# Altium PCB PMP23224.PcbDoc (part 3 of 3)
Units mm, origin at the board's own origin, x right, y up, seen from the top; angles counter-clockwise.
Board outline 180 x 75 mm, 4 copper layers (Top Layer, Signal Layer 1, Signal Layer 2, Bottom Layer), stack 1.565 mm thick; 189 components, 98 nets, 443 pads, 89 vias.
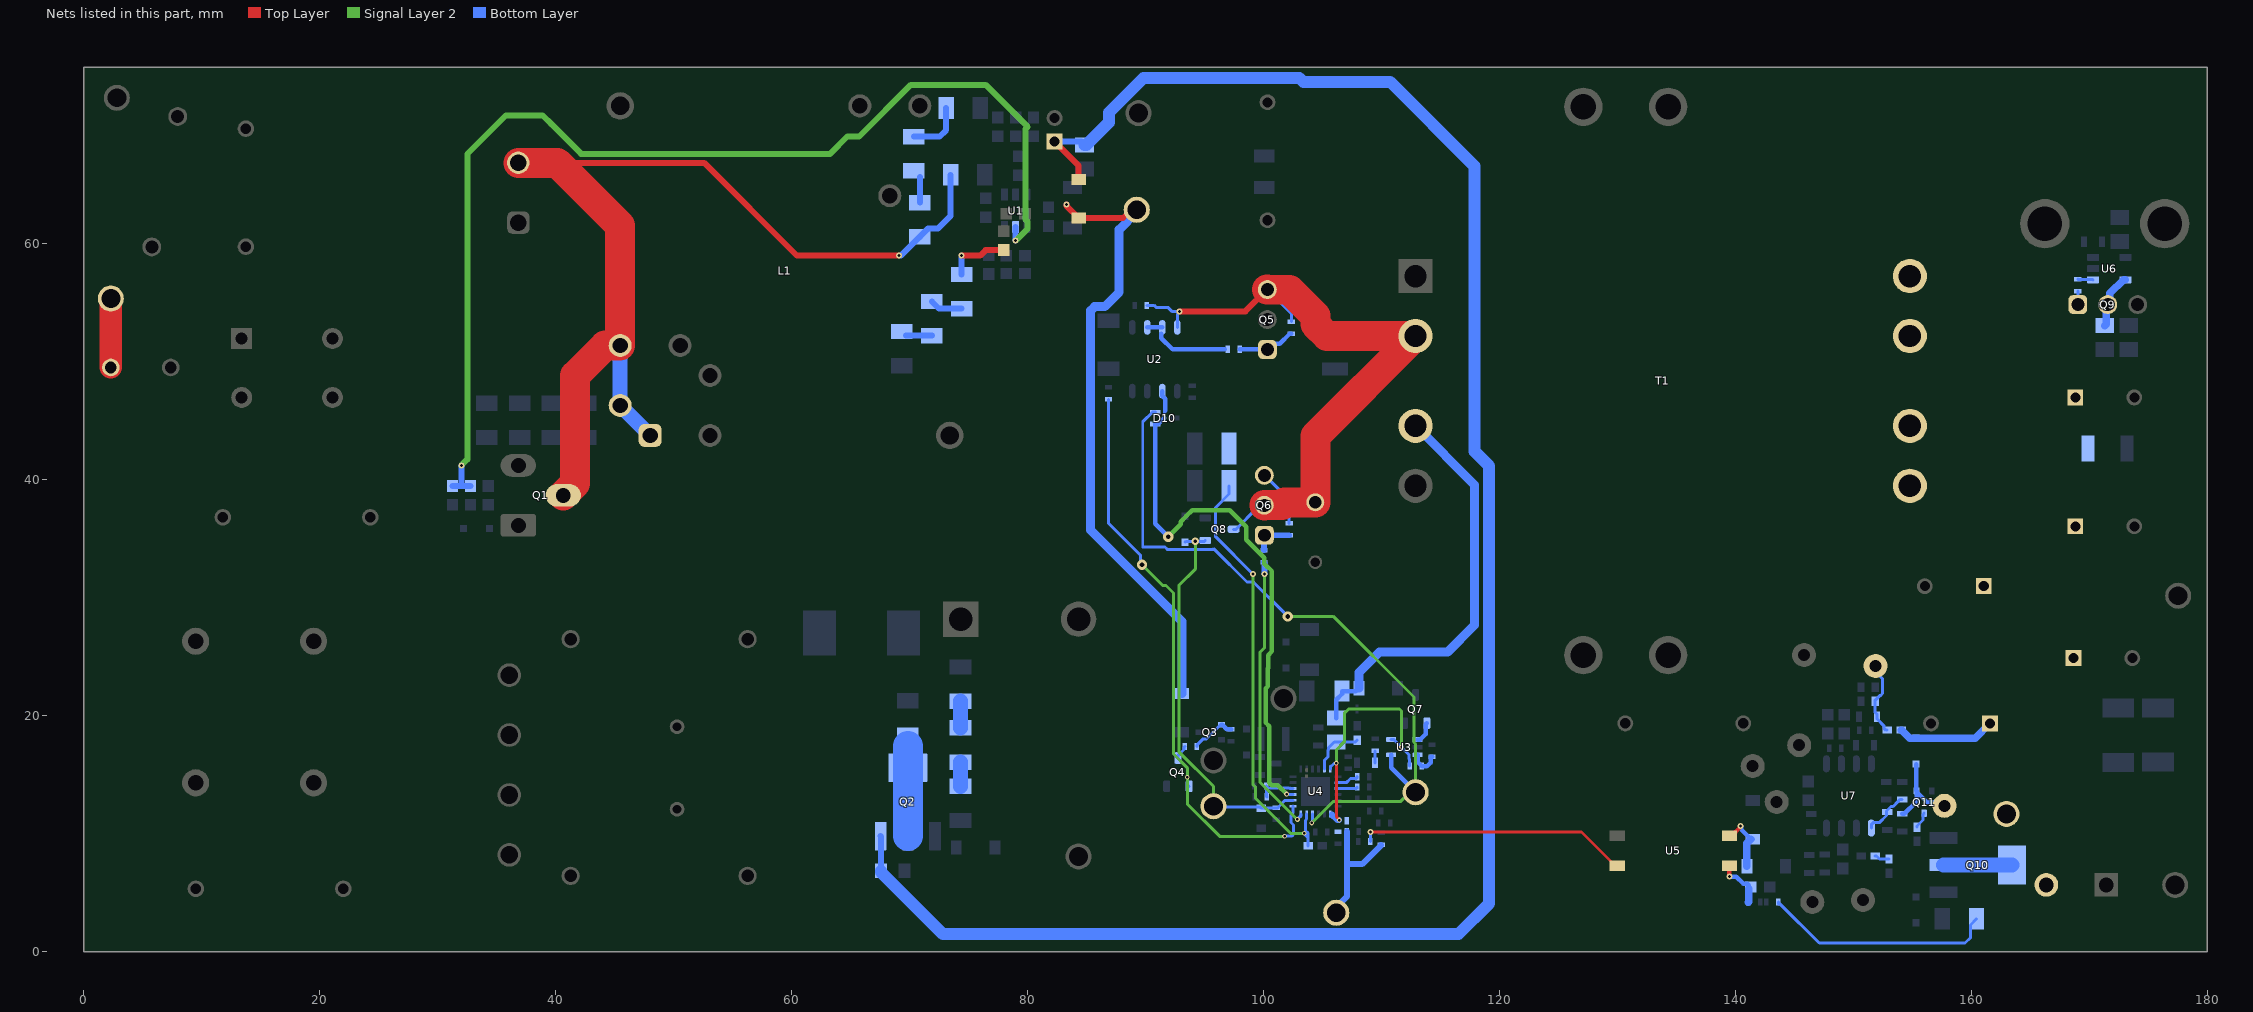
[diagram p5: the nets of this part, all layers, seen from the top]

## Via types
v1: diameter 0.508, hole 0.254, Top Layer to Bottom Layer, 41 vias
v2: diameter 0.406, hole 0.203, Top Layer to Bottom Layer, 23 vias
v3: diameter 1.27, hole 0.711, Top Layer to Bottom Layer, 12 vias
v4: diameter 0.5, hole 0.2, Top Layer to Bottom Layer, 5 vias
v5: diameter 0.864, hole 0.406, Top Layer to Bottom Layer, 4 vias
v6: diameter 2.54, hole 1.27, Top Layer to Bottom Layer, 2 vias
v7: diameter 0.635, hole 0.305, Top Layer to Bottom Layer, 2 vias

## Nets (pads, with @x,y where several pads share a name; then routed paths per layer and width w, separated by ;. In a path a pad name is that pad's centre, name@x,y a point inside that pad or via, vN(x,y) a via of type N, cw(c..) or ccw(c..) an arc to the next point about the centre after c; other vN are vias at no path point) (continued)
NetD19_2: D19.2 Q11.1 R68.2 TP20.1 | length 7.7
  Bottom Layer w0.381: R68.2@154.145,11.696 154.336,11.696 155.363,12.724 Q11.1@155.363,13.576 ; D19.2@155.326,15.902 155.345,15.884 155.345,13.659 Q11.1@155.363,13.641 Q11.1@155.363,13.576 ; TP20.1@157.734,12.369 157.418,12.685 156.253,12.685 Q11.1@155.363,13.576
NetF1_1: F1.1 TP_L1.1 | length 5.8
  Top Layer w1.905: F1.1@2.286,49.53 TP_L1.1@2.286,55.372
NetQ2_2: Q2.2 Q2.4 R20.1 | length 7.7
  Bottom Layer w2.54: Q2.2@69.85,9.8 Q2.4@69.85,15.6 69.85,17.458
NetQ3_1: Q3.1 R25.1 R26.2 | length 3.9
  Bottom Layer w0.254: R26.2@94.353,17.389 94.353,17.503 94.894,18.044 95.164,18.044 96.376,19.256 Q3.1@96.441,19.256
  Bottom Layer w0.381: Q3.1@96.441,19.256 96.506,19.256 96.899,18.864 R25.1@97.255,18.864
NetQ4_3: Q4.3 R26.1 | length 1.2
  Bottom Layer w0.254: Q4.3@92.745,16.421 92.745,16.621 93.273,17.15 93.273,17.325 R26.1@93.337,17.389
NetQ5_1: Q5.1 R28.2 R29.2 | length 5
  Bottom Layer w0.381: R28.2@97.974,51.067 100.317,51.067 Q5.1@100.33,51.054 100.81,51.534 101.377,51.534 102.248,52.405 R29.2@102.362,52.405
NetQ6_1: Q6.1 R30.2 R31.2 | length 3.4
  Bottom Layer w0.508: R30.2@100.055,34.036 100.065,34.047 100.065,35.295 Q6.1@100.076,35.306 R31.2@102.181,35.306
NetQ7_1: Q7.1 U3.1 | length 1.8
  Bottom Layer w0.381: U3.1@113.078,17.988 113.303,17.988 113.744,18.428 113.744,19.265 Q7.1@113.853,19.374
NetQ9_1: Q9.1 R51.1 | length 1.1
  Bottom Layer w0.254: Q9.1@169.037,54.864 R51.1@169.037,56.007
NetQ11_3: Q11.3 R66.1 | length 1.4
  Bottom Layer w0.254: R66.1@155.401,10.564 155.401,10.664 155.905,11.168 155.905,11.633 Q11.3@156.013,11.741
NetR1_1: R1.1 R2.2 | length 2.2
  Bottom Layer w0.508: R1.1@70.866,63.507 R2.2@70.866,65.687
NetR2_1: R2.1 R5.2 | length 4.8
  Bottom Layer w0.508: R2.1@70.358,69.095 72.538,69.095 73.099,69.656 R5.2@73.099,71.521
NetR3_1: R3.1 R7.1 U1.5 | length 95.4
  Signal Layer 2 w0.508: v1(32.004,41.229) 32.512,41.737 32.512,67.63 35.775,70.893 38.901,70.893 39.609,70.185 39.624,70.185 42.164,67.645 63.261,67.645 64.731,69.115 65.732,69.115 70.104,73.487 76.454,73.487 80.01,69.931 79.81,69.731 79.81,62.091 80.01,61.891 80.01,61.295 v1(78.994,60.279)
  Bottom Layer w0.508: R7.1@31.242,39.489 32.004,39.489 ; v1(32.004,41.229) 32.004,39.489 ; R3.1@32.766,39.489 32.004,39.489 ; v1(78.994,60.279) U1.5@78.994,61.444
NetR6_1: R6.1 R9.2 | length 2.2
  Bottom Layer w0.508: R6.1@69.702,52.225 R9.2@71.882,52.225
NetR9_1: R9.1 R15.2 | length 2.8
  Bottom Layer w0.508: R9.1@71.882,55.125 72.496,54.511 R15.2@74.422,54.511
NetR15_1: R15.1 R16.2 | length 5.3
  Top Layer w0.508: v1(74.422,59.009) 75.984,59.009 76.454,59.479 77.216,59.479 R16.2@77.978,59.479
  Bottom Layer w0.508: R15.1@74.422,57.411 v1(74.422,59.009)
NetR19_1: R19.1 R22.2 | length 2.3
  Bottom Layer w1.27: R22.2@74.328,18.976 R19.1@74.328,21.237
NetR22_1: R22.1 R23.2 | length 2.1
  Bottom Layer w1.27: R23.2@74.328,14.021 R22.1@74.328,16.076
NetR28_1: R28.1 U2.6 U2.7 | length 7.4
  Bottom Layer w0.381: U2.6@90.154,52.927 U2.7@91.424,52.927 ; U2.7@91.339,52.407 91.339,52.016 92.301,51.054 96.704,51.054
NetR32_1: R32.1 R34.1 U3.3 | length 2.6
  Bottom Layer w0.381: U3.3@113.078,16.688 113.078,16.085 113.459,15.704 113.855,15.704 114.186,16.034 114.186,16.51 R34.1@114.3,16.51
NetR41_2: R41.2 U5.4 | length 22.9
  Top Layer w0.254: v1(109.058,10.147) 126.959,10.147 129.802,7.303 U5.4@130.002,7.303
  Bottom Layer w0.254: R41.2@109.058,9.332 v1(109.058,10.147)
NetR43_2: R43.2 RT1.1 | length 1
  Bottom Layer w0.254: RT1.1@109.474,16.002 R43.2@109.474,17.018
NetR51_2: R51.2 U6.1 | length 1.3
  Bottom Layer w0.254: R51.2@169.037,57.023 169.067,56.992 170.298,56.992 U6.1@170.329,56.962
NetR52_1: R52.1 R53.2 R55.2 TP13.1 | length 6.5
  Bottom Layer w0.254: TP13.1@151.892,24.229 151.892,23.748 152.489,23.151 152.489,21.893 152.298,21.701 152.235,21.701 151.862,21.328 R53.2@151.862,21.228 151.862,20.275 152.024,20.113 R55.2@152.024,19.923 152.024,19.732 152.591,19.165 152.591,18.953 152.764,18.78 R52.1@152.864,18.78
NetR61_1: R61.1 R65.2 U7.5 | length 4
  Bottom Layer w0.254: U7.5@151.53,10.483 151.53,10.774 151.69,10.934 152.211,10.934 152.818,11.541 152.818,11.731 152.818,11.922 153.21,12.314 153.388,12.314 153.822,12.747 153.822,12.768 153.945,12.891 R61.1@154.145,12.891
NetR63_1: R63.1 R64.2 | length 1.3
  Bottom Layer w0.254: R64.2@151.862,8.112 151.962,8.112 152.216,7.858 R63.1@153.04,7.858
OPTO_AN: R58.1 R59.1 U5.1 | length 4.3
  Top Layer w0.381: v1(139.502,6.39) U5.1@139.502,7.303
  Bottom Layer w0.381: v1(139.502,6.39) 139.527,6.365 140.093,6.365 140.694,5.764 141.009,5.764 141.136,5.637 R58.1@141.136,5.322
  Bottom Layer w0.635: R59.1@141.102,4.21 141.136,4.243 R58.1@141.136,5.322
OPTO_CA: D17.2 D18.2 U5.2 | length 5.4
  Top Layer w0.381: U5.2@139.502,9.843 139.702,9.843 140.438,10.579 140.438,10.626 v1(140.462,10.651)
  Bottom Layer w0.381: v1(140.462,10.651) 140.486,10.626 140.486,10.378 141.325,9.539 D17.2@141.478,9.539
  Bottom Layer w0.635: D18.2@140.989,7.258 140.989,9.202 D17.2@141.325,9.539
P13: C28.1 D14.1 D15.1 Q8.1 TP6.1 U4.14 | length 33.2
  Signal Layer 2 w0.254: v7(94.22,34.804) 94.22,32.433 92.83,31.043 92.83,16.944 95.758,14.017 TP6.1@95.758,12.334
  Bottom Layer w0.254: D14.1@93.345,34.714 93.42,34.789 94.991,34.789 Q8.1@95.066,34.864 ; TP6.1@95.758,12.334 95.842,12.25 99.738,12.25 D15.1@99.822,12.166 99.835,12.179 101.079,12.179 C28.1@101.092,12.192 101.206,12.192 101.27,12.255 101.27,12.271 101.833,12.834 U4.14@102.514,12.834
PWMH: D10.1 U2.2 U4.15 | length 47.1
  Signal Layer 2 w0.381: v5(91.929,35.178) 92.991,36.239 92.991,36.452 93.475,36.937 93.475,36.948 93.96,37.433 97.129,37.433 98.546,36.017 98.546,34.919 100.054,33.41 100.075,33.41 ; 100.076,33.409 100.076,32.872 100.299,32.648 100.343,32.648 100.72,32.271 100.72,25.461 100.406,25.146 100.406,24.036 100.382,24.012 100.382,22.51 100.212,22.34 100.212,19.396 100.484,19.123 100.484,16.73 100.484,14.337 100.708,14.114 101.216,14.114 v2(101.966,13.364)
  Bottom Layer w0.254: 91.576,45.278 91.576,45.368 91.631,45.423 91.631,45.811 91.686,45.866 ; v2(101.966,13.364) 101.989,13.341 102.507,13.341 U4.15@102.514,13.334
  Bottom Layer w0.381: U2.2@91.424,47.527 91.424,47.137 91.686,46.875 91.686,45.866 ; 91.576,45.278 91.576,45.23 91.084,44.739 D10.1@90.834,44.739 90.834,36.272 v5(91.929,35.178)
PWML: R30.1 U4.12 | length 23.9
  Signal Layer 2 w0.254: v1(100.076,32.004) 100.076,25.75 99.694,25.368 99.694,14.396 v2(102.875,11.215)
  Bottom Layer w0.254: v2(102.875,11.215) 102.875,11.229 103.164,11.518 U4.12@103.164,11.684
  Bottom Layer w0.508: R30.1@100.055,33.02 100.076,32.999 v1(100.076,32.004)
RDM: R44.2 U4.3 | length 1.7
  Bottom Layer w0.254: U4.3@106.314,13.834 107.886,13.834 107.95,13.897 R44.2@107.95,13.97
REF: C27.2 C32.1 R32.2 R40.2 R46.2 TP9.1 U3.5 U4.7 U4.24 | length 33
  Top Layer w0.254: v2(106.172,15.993) 106.172,11.453 106.422,11.203 v2(106.422,11.162)
  Signal Layer 2 w0.254: v2(106.172,15.993) 106.172,17.106 106.857,17.792 106.857,20.21 107.222,20.574 111.531,20.574 111.704,20.401 v2(111.704,17.366)
  Bottom Layer w0.254: U4.24@105.664,15.484 105.664,15.65 105.978,15.964 106.143,15.964 v2(106.172,15.993) ; U3.5@110.828,17.988 111.053,17.988 112.326,16.715 112.326,16.382 112.395,16.313 R32.2@112.395,15.748
  Bottom Layer w0.508: 105.803,11.626 106.268,11.162 v2(106.422,11.162) ; TP9.1@106.172,3.302 106.172,3.763 107.075,4.665 107.075,7.426 ; R40.2@107.075,10.186 107.075,7.426 ; R46.2@109.982,9.052 109.982,9.039 108.368,7.426 107.075,7.426
RTZ: R42.2 U4.2 | length 1.9
  Bottom Layer w0.254: U4.2@106.314,14.334 107.026,14.334 107.379,14.687 107.886,14.687 107.95,14.75 R42.2@107.95,14.834
RUN: D10.2 TP8.1 U3.4 U4.10 | length 63.2
  Signal Layer 2 w0.254: v5(102.052,28.429) 105.915,28.429 112.754,21.59 112.754,17.727 112.903,17.579 TP8.1@112.903,13.521 112.395,13.521 111.598,12.725 105.897,12.725 v2(104.094,10.922)
  Bottom Layer w0.254: D10.2@90.834,45.739 90.584,45.739 89.768,44.922 89.768,34.308 91.664,34.308 91.884,34.087 95.721,34.087 95.793,34.159 98.599,31.353 99.129,31.353 v5(102.052,28.429) ; v2(104.094,10.922) 104.094,10.963 104.157,11.026 104.157,11.677 U4.10@104.164,11.684
  Bottom Layer w0.381: U3.4@110.828,16.688 110.828,15.596 TP8.1@112.903,13.521
S13: Q4.1 R27.1 U4.13 | length 50.8
  Signal Layer 2 w0.254: v5(89.694,32.811) 91.462,31.043 91.746,31.043 92.376,30.413 92.376,16.756 93.545,15.588 v2(93.545,14.783) 93.545,12.522 96.285,9.782 v2(101.793,9.782)
  Bottom Layer w0.254: R27.1@86.868,46.817 86.868,36.321 89.578,33.612 89.578,32.927 v5(89.694,32.811) ; v2(93.545,14.783) 93.574,14.754 93.574,14.142 Q4.1@93.695,14.021 ; v2(101.793,9.782) 101.822,9.811 102.434,9.811 102.555,9.932 102.545,9.942 102.545,10.745 102.345,10.945 102.345,11.577 102.514,11.746 U4.13@102.514,12.334
SWS: C26.1 R37.1 U4.16 | length 3.2
  Bottom Layer w0.254: C26.1@100.246,14.04 100.246,13.934 C26.1@100.266,13.914 ; R37.1@100.286,13.13 100.266,13.15 C26.1@100.266,13.914 ; U4.16@102.514,13.834 102.507,13.841 102.239,13.841 102.186,13.894 101.695,13.894 101.672,13.871 100.309,13.871 C26.1@100.266,13.914
Vaux: D9.2 D11.2 R38.2 T1.3 | length 35.8
  Bottom Layer w0.381: R38.2@106.172,19.812 106.172,21.356 106.664,21.848 D9.2@106.664,22.098 107.837,22.098 D11.2@108.091,22.352
  Bottom Layer w0.762: D11.2@108.091,22.352 108.091,23.661 109.83,25.4 115.603,25.4 117.889,27.686 117.889,39.579 T1.3@112.89,44.577
VCC_PFC: C11.1 C16.1 D5.1 Q2.3 R17.2 | length 166.2
  Top Layer w0.508: C11.1@82.296,68.677 84.328,66.645 D5.1@84.328,65.472
  Bottom Layer w0.508: Q2.3@67.55,9.8 67.563,9.787 67.563,6.871 C16.1@67.575,6.858 ; C11.1@82.296,68.677 R17.2@84.566,68.677
  Bottom Layer w1.016: C16.1@67.575,6.858 67.575,6.749 72.835,1.489 116.526,1.489 119.126,4.089 119.126,41.181 117.889,42.418 117.889,66.596 110.744,73.741 103.377,73.741 103.035,74.083 89.838,74.083 86.893,71.137 86.893,70.298 85.001,68.407 R17.2@84.836,68.407
VD: C7.1 D2.3 L1.1 L1.11 L1.12 Q1.2 R1.2 | length 86.6
  Top Layer w0.508: 40.132,66.883 52.578,66.883 60.452,59.009 v1(69.088,59.009)
  Top Layer w2.54: D2.3@36.83,66.883 40.132,66.883 45.466,61.549 L1.11@45.466,51.389 44.196,51.389 41.656,48.849 41.656,39.705 Q1.2@40.64,38.689
  Bottom Layer w0.508: v1(69.088,59.009) 69.268,59.009 R1.2@70.866,60.607 71.554,61.295 72.39,61.295 73.48,62.385 C7.1@73.48,65.867
  Bottom Layer w1.27: L1.11@45.466,51.389 L1.12@45.466,46.309 L1.1@48.006,43.769
VDD: D5.2 D7.1 TP1.1 | length 53.1
  Top Layer w0.508: v1(83.312,63.327) 83.312,63.213 D5.2@84.328,62.197 88.095,62.197 88.798,62.9 TP1.1@89.258,62.9
  Bottom Layer w0.762: TP1.1@89.258,62.9 89.258,62.723 87.757,61.222 87.757,55.919 86.533,54.695 85.682,54.695 85.342,54.355 85.342,35.731 93.075,27.998 D7.1@93.075,21.881
VDRAIN: Q9.2 R48.1 T1.7 T1.8 U6.5 | length 4.7
  Bottom Layer w0.635: R48.1@171.323,53.086 171.45,53.213 171.45,54.737 Q9.2@171.577,54.864 171.762,55.049 171.762,55.81 172.914,56.962 U6.5@173.079,56.962
Vout: C33.1 C34.1 C35.1 C36.1 C37.1 C38.1 C45.1 D19.1 J1.2 Q10.2 Q10.4 R52.2 R54.2 T1.5 T1.6 TP10.1 | length 33.9
  Bottom Layer w0.254: C45.1@143.642,4.21 143.642,4.096 143.706,4.032 143.82,4.032 147.123,0.73 159.48,0.73 159.931,1.181 159.931,2.271 R54.2@160.454,2.794
  Bottom Layer w0.635: R52.2@154.064,18.78 154.129,18.78 154.807,18.102 D19.1@155.326,18.102 160.339,18.102 C37.1@161.595,19.358
  Bottom Layer w1.27: Q10.2@157.654,7.35 Q10.4@163.454,7.35
Vrs: Q6.3 R31.1 R33.2 R35.2 R36.2 U4.11 | length 42.4
  Signal Layer 2 w0.254: v1(99.123,32.004) 99.123,14.145 99.343,13.925 99.343,12.982 102.285,10.04 v2(103.458,10.04)
  Bottom Layer w0.254: R35.2@97.081,39.497 97.081,38.797 95.95,37.666 95.95,35.178 v1(99.123,32.004) ; Q6.3@100.076,40.386 100.104,40.386 102.181,38.309 R31.1@102.181,36.322 ; v2(103.458,10.04) 103.458,9.999 103.794,9.664 103.794,9.322 ; U4.11@103.664,11.684 103.657,11.677 103.657,11.234 103.564,11.142 103.564,10.263 103.794,10.033 103.794,9.322 ; R33.2@103.794,8.982 103.794,9.322
VS: R38.1 R39.2 U4.23 | length 4.7
  Bottom Layer w0.254: U4.23@105.164,15.484 105.164,16.216 105.458,16.51 105.458,17.066 105.499,17.107 105.499,17.272 106.007,17.78 R38.1@106.172,17.78 107.788,17.78 R39.2@107.95,17.942
Vswn: C19.2 Q5.3 Q6.2 Q8.3 R29.1 T1.2 TP3.1 U2.8 | length 56.3
  Top Layer w0.508: v1(92.889,54.293) 98.461,54.293 Q5.3@100.302,56.134
  Top Layer w2.54: Q6.2@100.076,37.846 100.091,37.861 101.556,37.861 101.795,38.1 TP3.1@104.394,38.1 104.394,43.701 T1.2@112.89,52.197 105.394,52.197 104.394,53.197 104.394,53.916 102.19,56.119 100.345,56.119 Q5.3@100.33,56.134 Q5.3@100.302,56.134
  Bottom Layer w0.254: C19.2@90.121,54.795 90.732,54.795 90.93,54.597 91.929,54.597 92.233,54.293 v1(92.889,54.293) 92.889,54.225 92.694,54.029 U2.8@92.694,52.927 ; Q8.3@97.466,35.814 97.666,35.814 99.44,37.588 99.818,37.588 Q6.2@100.076,37.846 ; Q5.3@100.33,56.134 100.358,56.134 102.362,54.13 R29.1@102.362,53.421
pads on no net: H1.MH1 H1.MH2 L1.3 L1.4 L1.7 L1.8 L1.10 L1.14 T1.9 T1.12

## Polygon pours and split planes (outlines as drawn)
Vrs on Bottom Layer "BOTTOM_LAYER_VRS_P104" (solid, pour order 104): 95.828,46.676 95.828,36.914 98.654,36.914 98.665,36.903 98.876,37.114 98.876,39.046 102.682,39.046 102.706,39.022 103.124,39.439 103.124,46.676
GND_SEC on Bottom Layer "SGND" (solid, pour order 119): 179.832,74.168 179.324,74.676 163.83,74.676 163.322,74.168 163.322,58.674 144.78,40.132 144.78,14.415 179.832,14.415
GND_SEC on Bottom Layer "BOTTOM_LAYER_GND_SEC_P116" (solid, pour order 116): 146.59,25.444 146.641,25.494 156.242,25.494 156.242,12.81 156.242,1.485 146.469,1.598 146.469,25.068 146.844,25.444
Vout on Bottom Layer "BOTTOM_LAYER_VOUT_P110" (solid, pour order 110): 149.905,49.008 149.956,49.058 159.557,49.058 159.557,36.374 159.609,36.322 149.784,36.322 149.784,48.632 150.159,49.008
BAT_GND on Bottom Layer "BOTTOM_LAYER_BAT_GND_P113" (solid, pour order 113): 166.441,18.504 166.479,18.542 180.086,18.542 180.086,0.254 163.83,0.254 163.83,9.657 166.385,12.212 166.385,18.504
NetC24_1 on Bottom Layer "BOTTOM_LAYER_NETC24_1_P058" (solid, pour order 58): 95.066,18.224 94.612,17.77 94.612,14.473 96.363,14.473 97.734,15.844 100.408,15.844 100.735,15.517 100.735,14.963 103.333,14.963 103.362,15.536 103.362,16.09 101.734,16.09 100.664,17.161 99.36,17.161 99.36,18.214 99.27,18.304 99.169,18.203 95.066,18.203
BIN on Bottom Layer "BOTTOM_LAYER_BIN_P092" (solid, pour order 92): 104.734,24.439 104.734,17.988 105.164,17.988 105.164,17.119 105.063,17.018 101.32,17.018 101.32,18.852 101.029,19.143 100.679,19.143 100.679,21.427 100.679,24.439
REF on Bottom Layer "BOTTOM_LAYER_REF_P080" (solid, pour order 80): 106.314,12.192 106.314,11.542 106.422,11.434 107.503,11.434 107.503,9.644 107.524,9.623 105.856,9.623 105.856,10.67 105.41,10.67 105.41,12.171 105.431,12.192
IC_GND on Bottom Layer "BOTTOM_LAYER_IC_GND_P112" (solid, pour order 112): 96.853,14.963 96.853,7.782 111.471,7.782 111.228,8.025 111.228,20.136 107.626,20.136 107.503,20.014 107.503,17.018 106.422,17.018 106.664,16.776 106.664,14.963
GND on Bottom Layer "GND" (solid, pour order 121): 28.956,4.653 70.104,4.653 72.136,6.685 95.758,6.685 116.84,6.685 116.84,43.769 110.324,50.284 91.186,50.284 91.186,74.503 69.088,74.503 67.31,74.503 29.718,74.503 29.21,73.995 29.21,46.055 27.94,44.785 27.94,32.085 31.75,28.275 37.338,28.275 39.878,25.735 39.878,11.003 38.354,9.479 29.718,9.479 28.956,8.717
VDRAIN on Bottom Layer "VD_SR2" (solid, pour order 2): 151.944,50.592 151.182,51.354 151.182,59.228 151.69,59.736 157.278,59.736 157.278,50.592
Vout on Bottom Layer "Vout" (solid, pour order 16): 159.004,49.102 159.004,0.768 170.229,0.655 170.96,49.102
NetC8_2 on Bottom Layer "C114_2" (solid, pour order 38): 33.02,44.277 32.766,44.023 32.766,41.013 34.328,39.451 37.084,39.451 39.116,41.483 42.672,41.483 43.688,42.499 43.688,44.023 43.434,44.277
HV on Bottom Layer "HS" (solid, pour order 40): 104.698,50.931 104.698,63.969 117.094,63.969 117.094,51.643 111.252,51.643 105.41,51.643
GND on Bottom Layer "GND" (solid, pour order 115): 89.408,63.073 90.17,62.311 90.17,60.279 88.646,58.755 88.646,53.929 87.884,53.167 80.772,53.167 80.264,52.659 80.264,41.483 77.724,38.943 61.468,38.943 60.96,38.435 60.96,34.625 62.992,32.593 65.532,32.593 66.294,31.831 66.294,29.799 51.054,29.799 46.482,25.227 40.64,25.227 37.846,28.021 37.846,31.323 46.228,39.705 53.086,39.705 55.372,41.991 55.372,48.849 50.292,53.929 44.704,53.929 43.434,52.659 43.434,45.547 43.18,45.293 33.782,45.293 33.02,46.055 33.02,53.421 41.148,61.549 55.626,61.549 61.214,55.961 61.214,51.389 65.786,46.817 73.152,46.817 75.946,49.611 75.946,52.913 79.502,56.469 80.772,56.469 87.376,63.073
NetC6_1 on Bottom Layer "C108_1" (solid, pour order 60): 49.53,17.861 49.022,18.369 49.022,19.893 49.53,20.401 51.054,20.401 51.562,19.893 51.562,18.369 51.054,17.861
NetC5_1 on Bottom Layer "C107_1" (solid, pour order 84): 35.052,25.227 34.544,24.719 34.544,22.433 35.052,21.925 36.83,21.925 38.608,20.147 38.608,18.369 52.07,4.907 56.896,4.907 57.658,5.669 57.658,7.193 39.624,25.227
HV on Signal Layer 2 "SIGNAL_LAYER_2_HV_P044" (solid, pour order 44): 114.603,63.327 114.603,54.864 108.712,54.864 88.265,34.417 74.168,20.32 63.301,31.187 95.441,63.327
IC_GND on Signal Layer 2 "SIGNAL_LAYER_2_IC_GND_P032" (solid, pour order 32): 96.853,14.963 96.853,7.782 111.471,7.782 111.228,8.025 111.228,20.056 107.546,20.056 107.503,20.014 107.503,17.018 106.422,17.018 106.664,16.776 106.664,14.963
GND on Signal Layer 2 "GND" (solid, pour order 107): 28.956,4.653 29.718,3.891 69.342,3.891 72.136,6.685 95.758,6.685 101.854,0.589 123.952,0.589 124.206,0.843 124.206,16.337 120.396,20.147 120.396,40.213 111.255,49.354 91.186,49.354 91.186,65.105 81.788,74.503 69.088,74.503 67.31,74.503 29.718,74.503 29.21,73.995 29.21,46.055 27.94,44.785 27.94,32.085 31.75,28.275 37.338,28.275 39.878,25.735 39.878,11.003 38.354,9.479 29.718,9.479 28.956,8.717
GND_SEC on Signal Layer 2 "SGND" (solid, pour order 106): 179.832,74.168 179.324,74.676 163.83,74.676 163.322,74.168 163.322,58.674 144.78,40.132 144.78,1.016 179.832,1.016
NetC6_1 on Signal Layer 2 "C108_1" (solid, pour order 88): 49.53,17.861 49.022,18.369 49.022,41.737 52.832,45.547 54.864,45.547 57.912,42.499 57.912,29.037 57.912,23.703 52.07,17.861
HV on Signal Layer 2 "HV" (solid, pour order 72): 35.814,63.835 35.306,63.327 35.306,60.025 37.338,57.993 42.615,57.992 76.553,24.055 79.375,26.878 73.914,32.339 73.914,39.705 49.784,63.835
VDRAIN on Signal Layer 1 "VD_SR2" (solid, pour order 102): 151.86,50.459 151.098,51.221 151.098,59.095 151.606,59.603 157.664,59.603 157.664,57.217 172.886,57.217 172.886,52.324 157.205,52.205 157.194,50.459
IC_GND on Signal Layer 1 "SIGNAL_LAYER_1_IC_GND_P082" (solid, pour order 82): 96.853,14.963 96.853,7.782 111.471,7.782 111.228,8.025 111.228,20.056 107.546,20.056 107.503,20.014 107.503,17.018 106.422,17.018 106.664,16.776 106.664,14.963
GND on Signal Layer 1 "GND" (solid, pour order 123): 28.956,4.653 29.718,3.891 69.342,3.891 72.136,6.685 95.758,6.685 101.854,0.589 123.952,0.589 124.206,0.843 124.206,16.337 120.396,20.147 120.396,40.213 111.333,49.276 91.186,49.276 91.186,65.105 81.788,74.503 69.088,74.503 67.31,74.503 29.718,74.503 29.21,73.995 29.21,46.055 27.94,44.785 27.94,32.085 31.75,28.275 37.338,28.275 39.878,25.735 39.878,11.003 38.354,9.479 29.718,9.479 28.956,8.717
GND_SEC on Signal Layer 1 "SGND" (solid, pour order 122): 179.832,75 144.78,75 144.78,0.762 145.288,0.254 179.324,0.254 179.832,0.762
GND on Signal Layer 1 "GND" (solid, pour order 109): 89.408,63.073 90.17,62.311 90.17,60.533 88.646,59.009 88.646,53.929 87.884,53.167 80.772,53.167 80.264,52.659 80.264,41.483 77.724,38.943 72.644,38.943 71.882,39.705 71.882,45.547 75.946,49.611 75.946,52.913 79.502,56.469 80.772,56.469 87.376,63.073
GND on Signal Layer 1 "GND" (solid, pour order 111): 58.42,33.609 57.658,34.371 57.658,44.785 58.42,45.547 72.39,45.547 72.644,45.293 72.644,38.943 65.024,38.943 59.69,33.609
NetC5_1 on Signal Layer 1 "C107_1" (solid, pour order 90): 35.052,25.227 34.544,24.719 34.544,22.433 35.052,21.925 36.83,21.925 38.608,20.147 38.608,18.369 52.07,4.907 56.896,4.907 57.658,5.669 57.658,7.193 39.624,25.227
GND on Signal Layer 1 "GND" (solid, pour order 118): 40.386,25.989 40.894,25.481 51.562,25.481 59.944,33.863 59.69,34.117 59.69,43.261 58.166,44.785 57.658,44.785 45.974,33.101 43.434,33.101 40.386,30.053
Vrs on Top Layer "TOP_LAYER_VRS_P068" (solid, pour order 68): 95.828,46.676 95.828,36.914 98.654,36.914 98.665,36.903 98.876,37.114 98.876,39.046 102.682,39.046 102.706,39.022 103.124,39.439 103.124,46.817 95.968,46.817
BAT_GND on Top Layer "TOP_LAYER_BAT_GND_P108" (solid, pour order 108): 166.441,18.504 166.479,18.542 180.086,18.542 180.086,0.254 163.83,0.254 163.83,9.657 166.385,12.212 166.385,18.504
VDRAIN on Top Layer "VD_SR2" (solid, pour order 12): 151.86,50.459 151.098,51.221 151.098,59.095 151.606,59.603 157.664,59.603 157.664,57.217 172.886,57.217 172.886,52.324 157.205,52.205 157.194,50.459
Vout on Top Layer "TOP_LAYER_VOUT_P064" (solid, pour order 64): 149.86,49.008 149.911,49.058 159.512,49.058 159.512,36.374 159.564,36.322 149.738,36.322 149.738,48.632 150.114,49.008
Vout on Top Layer "Vout" (solid, pour order 86): 158.58,48.758 158.58,1.648 169.823,1.534 170.537,48.758
IC_GND on Top Layer "TOP_LAYER_IC_GND_P100" (solid, pour order 100): 96.853,14.963 96.853,7.782 111.471,7.782 111.228,8.025 111.228,20.056 107.546,20.056 107.503,20.014 107.503,17.018 106.422,17.018 106.664,16.776 106.664,14.963
GND on Top Layer "GND" (solid, pour order 120): 28.956,4.653 29.718,3.891 69.342,3.891 72.136,6.685 95.758,6.685 101.854,0.589 123.952,0.589 129.802,6.439 129.802,30.806 110.825,49.784 91.186,49.784 91.186,74.503 69.088,74.503 67.31,74.503 29.718,74.503 29.718,30.307 31.75,28.275 37.338,28.275 39.878,25.735 39.878,11.003 38.354,9.479 29.718,9.479 28.956,8.717
GND_SEC on Top Layer "sGND" (solid, pour order 114): 139.502,15.748 139.502,75.438 179.832,75.438 179.832,16.764 178.816,15.748
GND on Top Layer "GND" (solid, pour order 126): 89.408,63.073 90.17,62.311 90.17,60.533 88.646,59.009 88.646,53.929 87.884,53.167 80.772,53.167 80.264,52.659 80.264,41.483 77.724,38.943 72.644,38.943 71.882,39.705 71.882,45.547 75.946,49.611 75.946,52.913 79.502,56.469 80.772,56.469 87.376,63.073
GND on Top Layer "GND" (solid, pour order 124): 58.42,33.609 57.658,34.371 57.658,44.785 58.42,45.547 72.39,45.547 72.644,45.293 72.644,38.943 65.024,38.943 59.69,33.609
NetC6_1 on Top Layer "C108_1" (solid, pour order 36): 49.53,17.861 49.022,18.369 49.022,41.737 52.832,45.547 54.864,45.547 55.626,44.785 55.626,31.323 57.912,29.037 57.912,23.703 52.07,17.861
VD on Top Layer "VD" (solid, pour order 66): 39.116,37.927 39.878,37.165 43.18,37.165 49.022,43.007 49.022,49.611 49.022,62.057 44.958,66.121 44.958,68.407 43.434,69.931 35.814,69.931 35.306,69.423 35.306,65.613 35.814,65.105 38.862,65.105 41.402,62.565 41.402,51.897 40.132,50.627 40.132,40.213 39.116,39.197

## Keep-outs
Keep-Out Layer:
  text ".Layer_Name" at 14.656,-21.806 h1.52

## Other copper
Top Layer:
  pour cut-out: 104.902,14.986 104.945,15.029 104.945,16.68 105.202,16.68 105.164,16.718 105.164,18.707 108.443,18.707 108.585,18.565 108.585,17.018 106.422,17.018 105.458,16.054 105.458,15.04 105.404,14.986 104.864,14.986
  text ".Layer_Name" at 14.656,-21.806 h1.52
Signal Layer 1:
  pour cut-out: 104.902,14.986 104.945,15.029 104.945,16.68 105.202,16.68 105.164,16.718 105.164,18.707 108.443,18.707 108.585,18.565 108.585,17.018 106.422,17.018 105.458,16.054 105.458,15.04 105.404,14.986 104.864,14.986
Signal Layer 2:
  pour cut-out: 104.902,14.986 104.945,15.029 104.945,16.68 105.202,16.68 105.164,16.718 105.164,18.707 108.443,18.707 108.585,18.565 108.585,17.018 106.422,17.018 105.458,16.054 105.458,15.04 105.404,14.986 104.864,14.986
Bottom Layer:
  pour cut-out: 104.902,14.986 104.945,15.029 104.945,16.68 105.202,16.68 105.164,16.718 105.164,18.707 108.443,18.707 108.585,18.565 108.585,17.018 106.422,17.018 105.458,16.054 105.458,15.04 105.404,14.986 104.864,14.986
  text ".Layer_Name" at 14.656,-21.806 h1.52

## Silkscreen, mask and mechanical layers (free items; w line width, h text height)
Top Overlay:
  lines w0.178: 30.734,0.843 33.274,0.843 33.274,74.503 30.734,74.503 30.734,0.843 ; 94.487,61.214 94.515,26.243 97.055,26.243 97.027,61.214 94.487,61.214
  lines w0.254: 81.026,62.565 82.042,61.549 82.042,60.279
  text "'.PRJ_Number'.PCB_Rev" at 64.262,1.524 h2.75
  text ".Layer_Name" at 14.656,-21.806 h1.52
Bottom Overlay:
  lines w0.254: 26.924,37.984 27.686,38.746 27.686,43.064 26.924,43.826 ; 27.305,38.365 27.686,37.984 ; 27.686,37.927 29.718,37.927 30.226,38.435 ; 40.386,37.904 35.56,37.904 34.798,38.666 34.798,42.984 35.56,43.746 40.386,43.746 ; 63.754,67.391 68.834,67.391 ; 51.562,65.867 58.42,59.009 64.77,59.009 65.532,59.771 65.532,64.343 63.754,66.121 63.754,73.233 62.992,73.995 55.372,73.995 51.562,70.185 51.562,65.867
  text ".Layer_Name" at 14.656,-21.806 h1.52
Top Paste:
  text ".Layer_Name" at 14.656,-21.806 h1.52
Bottom Paste:
  text ".Layer_Name" at 14.656,-21.806 h1.52
Top Solder:
  text ".Layer_Name" at 14.656,-21.806 h1.52
  text ".Layer_Name" at 14.656,-21.806 h1.52
Bottom Solder:
  text ".Layer_Name" at 14.656,-21.806 h1.52
Drill Guide:
  text ".Layer_Name" at 14.656,-21.806 h1.52
M1 Board Outline:
  the board outline again, w0.178
  text ".Layer_Name" at 14.656,-21.806 h1.52
M2 Board Dimensions:
  rectangle: 0,-6.985 3.175,-3.81
  rectangle: 3.175,-10.16 12.7,-6.985
  lines w0.178: 0,-6.985 25.4,-6.985 ; 3.175,-10.16 3.175,-3.81 ; 6.35,-10.16 6.35,-3.81 ; 12.7,-10.16 12.7,-3.81 ; 19.05,-10.16 19.05,-3.81 ; 0,-10.16 25.4,-10.16 25.4,-3.81 0,-3.81 0,-10.16
  text ".Layer_Name" at 14.656,-21.806 h1.52
M3 3D STEP Top:
  text ".Layer_Name" at 14.656,-21.806 h1.52
M4 3D STEP Bottom:
  text ".Layer_Name" at 14.656,-21.806 h1.52
M5 Assembly Top:
  lines w0.254: -7.417,-23.626 160.223,-23.626 ; -7.417,-18.462 160.274,-18.462 ; -7.417,-13.297 -7.417,-28.791 94.31,-28.791 160.274,-28.791 160.274,-13.297 -7.404,-13.297 -7.404,-28.791 32.614,-28.791 ; 55.194,-28.791 55.194,-13.297 ; 87.376,-18.462 87.376,-13.297 ; 108.712,-18.462 108.712,-13.297 ; 124.511,-28.956 124.511,-23.804
  text "COMPONENTS MARKED 'DNP' SHOULD NOT BE POPULATED." at 29.299,-8.09 h1.52
  text "ASSEMBLY VARIANT:" at 29.286,-11.024 h1.52
  text ".VariantName" at 55.601,-11.024 h1.52
  text "PCB VIEWED FROM TOP SIDE" at -5.804,-16.654 h1.52
  text "BOARD #:" at 57.099,-16.654 h1.52
  text ".PRJ_Number" at 70.955,-16.654 h1.52
  text "REV:" at 92.405,-16.654 h1.52
  text ".PCB_Rev" at 99.809,-16.654 h1.52
  text "SVN REV:" at 113.69,-16.654 h1.52
  text ".VersionControl_RevNumber" at 126.543,-16.654 h1.52
  text "TID #:" at 57.099,-21.819 h1.52
  text ".TID" at 70.955,-21.819 h1.52
  text "PLOT NAME =" at -5.804,-27.034 h1.52
  text ".plot_File_Name" at 14.656,-27.034 h1.52
  text "GENERATED    :" at 57.15,-27.034 h1.52
  text ".Print_Date" at 79.235,-27.034 h1.52
  text ".Print_Time" at 97.752,-27.034 h1.52
  text "TEXAS INSTRUMENTS" at 129.87,-27.034 h1.52
M6 Assembly Bottom:
  lines w0.254: -7.429,-18.474 160.261,-18.474 ; -7.379,-23.639 160.261,-23.639 ; 28.334,-28.969 28.334,-23.817 ; 44.133,-18.474 44.133,-13.31 ; 65.468,-18.474 65.468,-13.31 ; 97.65,-28.804 97.65,-13.31 ; 120.231,-28.804 160.249,-28.804 160.249,-13.31 -7.429,-13.31 -7.429,-28.804 58.534,-28.804 160.261,-28.804 160.261,-13.31
  text "COMPONENTS MARKED 'DNP' SHOULD NOT BE POPULATED." at 154.991,-8.077 h1.52
  text ".VariantName" at 128.473,-11.024 h1.52
  text "ASSEMBLY VARIANT:" at 154.864,-11.024 h1.52
  text ".VersionControl_RevNumber" at 26.302,-16.667 h1.52
  text "SVN REV:" at 39.154,-16.667 h1.52
  text ".PCB_Rev" at 53.035,-16.667 h1.52
  text "REV:" at 60.439,-16.667 h1.52
  text ".PRJ_Number" at 81.89,-16.667 h1.52
  text "BOARD #:" at 95.745,-16.667 h1.52
  text "PCB VIEWED FROM BOTTOM SIDE" at 158.648,-16.667 h1.52
  text ".TID" at 81.89,-21.831 h1.52
  text "TID #:" at 95.745,-21.831 h1.52
  text "TEXAS INSTRUMENTS" at 22.974,-27.047 h1.52
  text ".Print_Time" at 55.093,-27.047 h1.52
  text ".Print_Date" at 73.609,-27.047 h1.52
  text "GENERATED    :" at 95.694,-27.047 h1.52
  text ".plot_File_Name" at 138.189,-27.047 h1.52
  text "PLOT NAME =" at 158.648,-27.047 h1.52
M9 Title Sheet:
  drawing of 57 lines, arcs and shapes, not listed
  text "1" at 18.792,204.127 h1.78
  text "2" at 82.182,204.127 h1.78
  text "3" at 145.411,204.127 h1.78
  text "4" at 209.08,204.127 h1.78
  text "5" at 272.555,204.127 h1.78
  text "6" at 336.182,204.127 h1.78
  text "A" at -10.579,175.095 h1.78
  text "A" at 365.341,175.095 h1.78
  text "B" at -10.579,114.643 h1.78
  text "B" at 365.341,114.643 h1.78
  text "C" at -10.579,54.318 h1.78
  text "C" at 365.341,54.318 h1.78
  text "PROJECT TITLE:" at 288.125,7.048 h1.14
  text ".PRJ_Title" at 289.395,3.662 h1.78
  text "DESIGNED FOR:" at 288.125,-0.597 h1.14
  text ".PRJ_Customer" at 289.395,-4.153 h1.78
  text "D" at -10.579,-5.88 h1.78
  text "D" at 365.341,-5.88 h1.78
  text "FILE NAME:" at 288.125,-8.217 h1.14
  text ".PCB_File_Name_No_Path" at 289.395,-11.265 h1.78
  text "Texas Instruments (TI) and/or its licensors do not warrant the accuracy or completeness of this specification" at 161.9,-15.376 h1.14
  text "ENGINEER:" at 288.125,-15.583 h1.14
  text "LAYOUT BY:" at 326.352,-15.583 h1.14
  text "or any information contained therein. TI and/or its licensors do not warrant that this design will meet" at 160.757,-18.237 h1.14
  text ".PRJ_Engineer" at 289.395,-19.52 h1.78
  text ".PCB_Layout" at 327.635,-19.52 h1.78
  text "the specifications, will be suitable for your application or fit for any particular purpose, or will operate in" at 160.757,-21.099 h1.14
  text ".Layer_Name" at 14.656,-21.806 h1.52
  text "ALTIUM DESIGNER VERSION:" at 326.352,-23.457 h1.14
  text "an implementation. TI and/or its licensors do not warrant that the design is production worthy. You should" at 160.757,-23.961 h1.14
  text "completely validate and test your design implementation to confirm the system functionality for your application." at 161.9,-26.822 h1.14
  text ".print_Scale" at 289.395,-26.843 h1.78
  text ".Application_BuildNumber" at 327.635,-26.843 h1.78
  text "1" at 18.792,-32.093 h1.78
  text "2" at 82.182,-32.093 h1.78
  text "3" at 145.411,-32.093 h1.78
  text "4" at 209.08,-32.093 h1.78
  text "5" at 272.555,-32.093 h1.78
  text "6" at 336.182,-32.093 h1.78
M10 Fab Notes:
  drawing of 189 lines, arcs and shapes, not listed
  text "DESIGN INFORMATION" at 314.503,161.447 h1.52
  text "MIN. TRACK WIDTH:" at 298.131,158.091 h1.52
  text "10" at 325.976,158.091 h1.52
  text "MIL" at 329.907,158.091 h1.52
  text "MIN. CLEARANCE:" at 298.131,154.938 h1.52
  text "0.2" at 324.452,154.938 h1.52
  text "mm" at 329.907,154.938 h1.52
  text "MIN. VIA PAD SIZE:" at 298.131,151.785 h1.52
  text "10" at 325.214,151.785 h1.52
  text "MIL" at 329.907,151.785 h1.52
  text "0.05mm (2MIL)" at 315.784,148.486 h1.52
  text "MINIMUM ANNULAR RING" at 289.769,148.277 h1.52
  text "EXTERNAL" at 333.768,148.277 h1.52
  text "PER" at 294.849,145.48 h1.52
  text "IPC-D-275 CLASS 2 LEVEL C" at 300.437,145.48 h1.52
  text "MIL, HOLES" at 338.238,142.928 h1.52
  text "+/-" at 328.27,142.709 h1.52
  text "+/-" at 349.961,142.709 h1.52
  text "REGISTRATION TOLERANCES:" at 289.769,142.682 h1.52
  text "METAL" at 320.243,142.682 h1.52
  text "5" at 334.879,142.683 h1.52
  text "3" at 356.037,142.683 h1.52
  text "MIL" at 358.99,142.682 h1.52
  text "HOLE SIZE TOLERANCE (UNLESS OTHERWISE SPECIFIED):" at 289.769,140.185 h1.52
  text "+/-" at 349.961,140.112 h1.52
  text "3" at 356.037,140.085 h1.52
  text "MIL" at 358.99,140.085 h1.52
  text "MATERIAL:" at 287.87,136.589 h1.52
  text "FR-4 High Tg" at 312.926,133.324 h1.52
  text "X" at 309.257,133.122 h1.52
  text "FR-408" at 298.563,133.007 h1.52
  text "OTHER" at 336.358,133.007 h1.52
  text "62 MIL (1.6mm) +/-10%" at 306.694,129.374 h1.52
  text "X" at 303.643,129.312 h1.52
  text "THICKNESS:" at 289.769,129.165 h1.52
  text "OTHER" at 339.33,129.165 h1.52
  text "TOLERANCE:" at 289.769,125.652 h1.52
  text "X" at 311.314,125.652 h1.52
  text "ANSI IPC-6012 TYPE 3 CLASS 2" at 315.836,125.652 h1.52
  text "OTHER +/-" at 315.835,121.989 h1.52
  text "BOW & TWIST:" at 289.769,118.302 h1.52
  text "X" at 311.314,118.302 h1.52
  text "ANSI IPC-6012 TYPE 3 CLASS 2" at 315.836,118.302 h1.52
  text "OTHER +/-" at 315.835,114.576 h1.52
  text "DRILLING:" at 287.87,111.258 h1.52
  text "NC_DRILL FILES" at 332.599,108.586 h1.52
  text "REFERENCE:" at 289.769,108.486 h1.52
  text "X" at 306.463,108.484 h1.52
  text "AS SHOWN" at 310.984,108.486 h1.52
  text "X" at 329.348,108.486 h1.52
  text "OTHER" at 340.168,104.873 h1.52
  text "PTH COPPER THICKNESS:" at 289.761,104.783 h1.52
  text "X" at 318.697,104.783 h1.52
  text "20-30 um" at 321.948,104.783 h1.52
  text "BOARD FINISH:" at 287.87,101.034 h1.52
  text "SILKSCREEN:" at 291.812,98.237 h1.52
  text "X" at 316.14,98.237 h1.52
  text "TOP" at 319.112,98.237 h1.52
  text "X" at 329.094,98.237 h1.52
  text "BOTTOM" at 332.091,98.237 h1.52
  text "SILKSCREEN COLOR:" at 291.812,94.295 h1.52
  text "X" at 316.115,94.295 h1.52
  text "WHITE" at 319.112,94.295 h1.52
  text "OTHER" at 332.091,94.295 h1.52
  text "X" at 319.442,90.652 h1.52
  text "GREEN" at 322.439,90.652 h1.52
  text "OTHER" at 338.136,90.652 h1.52
  text "SOLDER RESIST COLOR:" at 291.812,90.477 h1.52
  text "X" at 319.442,86.734 h1.52
  text "MATTE" at 322.439,86.734 h1.52
  text "SEMI-GLOSS" at 338.125,86.717 h1.52
  text "IMMERSION GOLD (ENIG)" at 314.819,82.345 h1.52
  text "ENEPIG" at 348.793,82.162 h1.52
  text "SURFACE FINISH:" at 287.87,82.136 h1.52
  text "IMM. TIN/SILVER OR EQUIV" at 296.24,78.649 h1.52
  text "OTHER" at 332.599,78.549 h1.52
  text "X" at 292.354,78.486 h1.52
  text "ARRAY/PANEL:" at 287.87,74.602 h1.52
  text "CUT AND TRIM PER M1 BOARD OUTLINE" at 314.819,74.393 h1.52
  text "N.C. ROUTE" at 314.819,70.94 h1.52
  text "X" at 332.295,70.94 h1.52
  text "V. SCORE" at 336.816,70.94 h1.52
  text "CERTIFICATION:" at 287.87,67.66 h1.52
  text "MATERIALS AND WORKMANSHIP FOR ALL PCBS" at 306.285,67.66 h1.52
  text "TO MEET OR EXCEED THE REQUIREMENTS OF:" at 306.285,65.271 h1.52
  text "X" at 297.078,62.003 h1.52
  text "ANSI IPC-A-600F CLASS ->" at 300.329,62.003 h1.52
  text "X" at 342.188,62.003 h1.52
  text "2" at 344.982,62.003 h1.52
  text "1" at 336.981,61.965 h1.52
  text "3" at 353.973,61.965 h1.52
  text "X" at 317.702,58.252 h1.52
  text "RoHS" at 320.953,58.252 h1.52
  text "OTHER" at 337.321,58.252 h1.52
  text "PER ORDER" at 347.407,58.252 h1.52
  text "ALL BOARDS MUST MEET OR EXCEED UL94-V0 REQUIREMENTS." at 288.569,54.345 h1.52
  text "PCB MUST BEAR THE UL94V-0 UL REGISTERED MATERIAL ID NUMBER" at 288.569,51.397 h1.52
  text "ADDITIONAL REQUIREMENTS:" at 287.87,47.094 h1.52
  text "MICROSECTION:" at 289.769,44.373 h1.52
  text "YES" at 312.775,44.373 h1.52
  text "REQUIRED" at 334.657,40.707 h1.52
  text "BARE BOARD ELEC. TEST:" at 289.769,40.634 h1.52
  text "X" at 320.04,40.64 h1.52
  text "NONE" at 322.935,40.634 h1.52
  text "PER ORDER" at 349.693,40.634 h1.52
  text "XX MIL VIAS REQUIRE NON-CONDUCTIVE FILL AND PLANARIZE" at 294.04,35.428 h1.5
  text "XX MIL VIAS REQUIRE CONDUCTIVE FILL AND PLANARIZE" at 294.243,32.787 h1.52
  text "OUTER XX MIL TRACES REQUIRE 50 OHM SINGLE-ENDED IMPEDANCE" at 294.218,28.637 h1.47
  text "LAYER 2 & 3 (INNER LAYERS) XX MIL WIDE, XX MIL SPACE / TRACES REQUIRE 100 OHM DIFFERENTIAL IMPEDANCE" at 294.015,22.65 h1.52
  text ".Layer_Name" at 14.656,-21.806 h1.52
M11 Gerber Information:
  lines w0.254: -7.417,-23.626 160.223,-23.626 ; -7.417,-18.462 160.274,-18.462 ; -7.417,-13.297 -7.417,-28.791 94.31,-28.791 160.274,-28.791 160.274,-13.297 -7.404,-13.297 -7.404,-28.791 32.614,-28.791 ; 55.194,-28.791 55.194,-13.297 ; 87.376,-18.462 87.376,-13.297 ; 108.712,-18.462 108.712,-13.297 ; 124.511,-28.956 124.511,-23.804
  text "ALL ARTWORK VIEWED FROM TOP SIDE" at -5.804,-16.654 h1.52
  text "BOARD #:" at 57.099,-16.654 h1.52
  text ".PRJ_Number" at 70.955,-16.654 h1.52
  text "REV:" at 92.405,-16.654 h1.52
  text ".PCB_Rev" at 99.809,-16.654 h1.52
  text "SVN REV:" at 113.69,-16.654 h1.52
  text ".VersionControl_RevNumber" at 126.543,-16.654 h1.52
  text "LAYER NAME =" at -5.804,-21.806 h1.52
  text "TID #:" at 57.099,-21.819 h1.52
  text ".TID" at 70.955,-21.819 h1.52
  text "PLOT NAME =" at -5.804,-27.034 h1.52
  text ".plot_File_Name" at 14.656,-27.034 h1.52
  text "GENERATED    :" at 57.15,-27.034 h1.52
  text ".Print_Date" at 79.235,-27.034 h1.52
  text ".Print_Time" at 97.752,-27.034 h1.52
  text "TEXAS INSTRUMENTS" at 129.87,-27.034 h1.52
M12 Stackup:
  drawing of 295 lines, arcs and shapes, not listed
  text "Layer" at 17.782,194.056 h1.52
  text "Name" at 28.194,194.056 h1.52
  text "Material" at 52.063,194.056 h1.52
  text "Thickness" at 73.902,194.056 h1.52
  text "Constant" at 90.407,194.056 h1.52
  text "Board Layer Stack" at 104.882,194.056 h1.52
  text "Top Overlay" at 28.194,191.008 h1.52
  text "Top Solder" at 28.194,187.96 h1.52
  text "Solder Resist" at 52.063,187.96 h1.52
  text "0.40mil" at 73.902,187.96 h1.52
  text "3.5" at 90.407,187.96 h1.52
  text "1" at 17.782,184.912 h1.52
  text "Top Layer" at 28.194,184.912 h1.52
  text "1.40mil" at 73.902,184.912 h1.52
  text "Dielectric 2" at 28.194,181.864 h1.52
  text "8.00mil" at 73.902,181.864 h1.52
  text "4.2" at 90.407,181.864 h1.52
  text "2" at 17.782,178.816 h1.52
  text "Signal Layer 1" at 28.194,178.816 h1.52
  text "1.40mil" at 73.902,178.816 h1.52
  text "Dielectric1" at 28.194,175.768 h1.52
  text "FR-4" at 52.063,175.768 h1.52
  text "40.00mil" at 73.902,175.768 h1.52
  text "4.8" at 90.407,175.768 h1.52
  text "3" at 17.782,172.72 h1.52
  text "Signal Layer 2" at 28.194,172.72 h1.52
  text "1.40mil" at 73.902,172.72 h1.52
  text "Dielectric 3" at 28.194,169.672 h1.52
  text "8.00mil" at 73.902,169.672 h1.52
  text "4.2" at 90.407,169.672 h1.52
  text "4" at 17.782,166.624 h1.52
  text "Bottom Layer" at 28.194,166.624 h1.52
  text "1.40mil" at 73.902,166.624 h1.52
  text "Bottom Solder" at 28.194,163.576 h1.52
  text "Solder Resist" at 52.063,163.576 h1.52
  text "0.40mil" at 73.902,163.576 h1.52
  text "3.5" at 90.407,163.576 h1.52
  text "Bottom Overlay" at 28.194,160.528 h1.52
  text ".Layer_Name" at 14.656,-21.806 h1.52
M13 Component Bodies Top:
  text ".Layer_Name" at 14.656,-21.806 h1.52
M14 Component Bodies Bottom:
  text ".Layer_Name" at 14.656,-21.806 h1.52
M15 Courtyards Top:
  text ".Layer_Name" at 14.656,-21.806 h1.52
M16 Courtyards Bottom:
  text ".Layer_Name" at 14.656,-21.806 h1.52
Drill Drawing:
  text ".Layer_Name" at 14.656,-21.806 h1.52
M17 Embedded Cavity:
  text ".Layer_Name" at 14.656,-21.806 h1.52
M18 Embedded Assembly:
  text ".Layer_Name" at 14.656,-21.806 h1.52
M19 Embedded Keepout:
  text ".Layer_Name" at 14.656,-21.806 h1.52

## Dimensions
29.718,74.503 to 24.638,63.559 on Signal Layer 2
30.734,0.843 to 31.806,16.256 on Signal Layer 2
30.734,74.503 to 30.734,0.843 on Top Overlay
0,-10.16 to 25.4,-10.16 on M2 Board Dimensions
0,0 to 0,75 on M2 Board Dimensions
0,0 to 180,0 on M2 Board Dimensions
